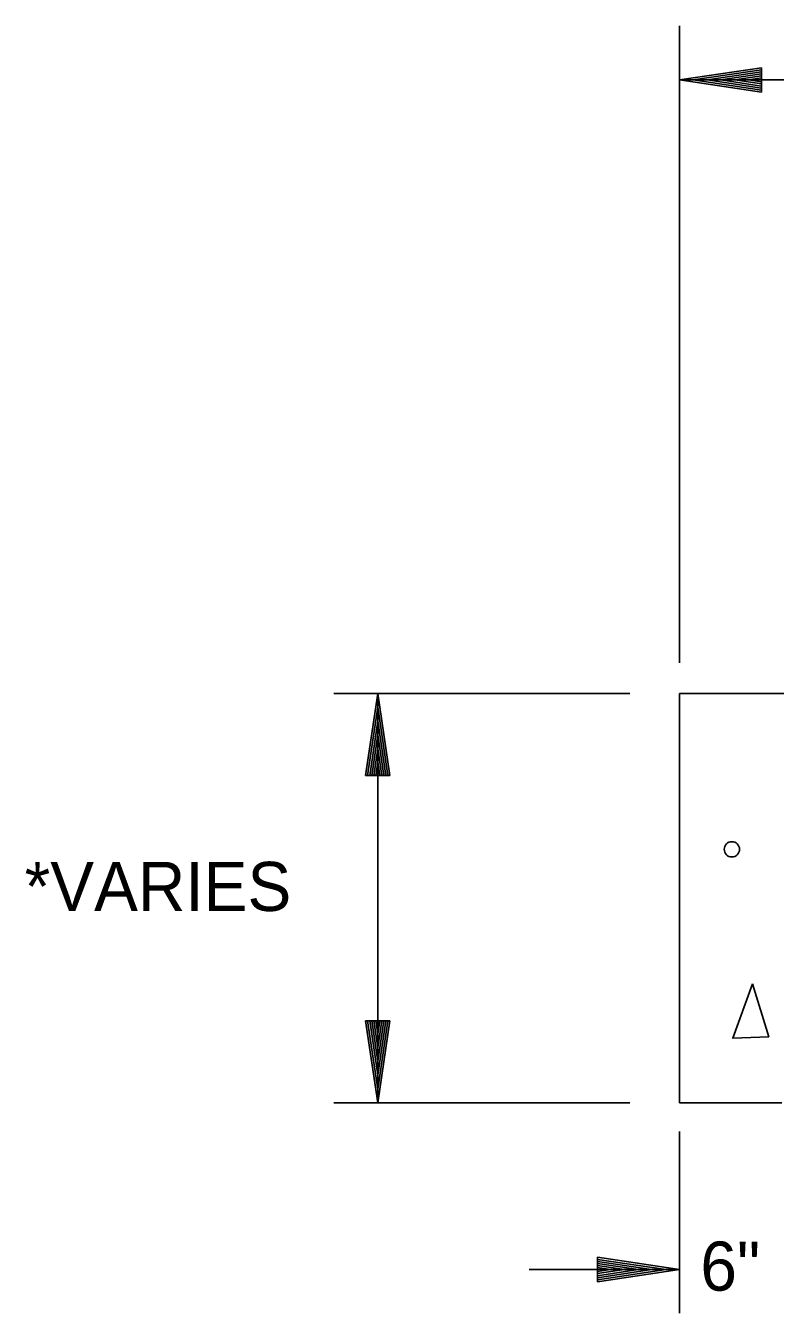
# Model space of a CAD drawing. Extents: x 3287 to 1767681, y -265 to 581440.
# Drawn here: x 3333.44 to 3351.75, y -240.26 to -208.81 of the extents above; entities that cross this region are included whole.
import ezdxf

# ---------------------------------------------------------------- set-up
doc = ezdxf.new("R2010")
doc.units = 0
doc.layers.add('Default', color=7, linetype='Continuous')

msp = doc.modelspace()

# ---------------------------------------------------------------- linework, layer by layer
at = {"layer": 'Default'}
for p, q in [((3349.405, -224.366), (3349.405, -208.806)), ((3351.407, -209.83), (3349.408, -210.13)), ((3351.407, -209.88), (3349.743, -210.13)), ((3351.407, -209.93), (3350.083, -210.13)), ((3351.407, -209.98), (3350.418, -210.13)), ((3351.407, -210.03), (3350.758, -210.13)), ((3351.407, -210.08), (3351.093, -210.13)), ((3351.407, -210.43), (3351.407, -209.83)), ((3349.405, -210.128), (3449.399, -210.128)), ((3351.407, -210.43), (3349.408, -210.13)), ((3351.407, -210.38), (3349.743, -210.13)), ((3351.407, -210.33), (3350.083, -210.13)), ((3351.407, -210.28), (3350.418, -210.13)), ((3351.407, -210.225), (3350.758, -210.13)), ((3351.407, -210.175), (3351.093, -210.13)), ((3348.198, -225.116), (3340.971, -225.116)), ((3341.738, -227.119), (3342.038, -225.119)), ((3342.338, -227.119), (3342.038, -225.119)), ((3342.039, -225.116), (3342.039, -235.116)), ((3349.405, -225.116), (3531.893, -225.116)), ((3349.405, -235.116), (3349.405, -225.116)), ((3341.788, -227.119), (3342.038, -225.449)), ((3342.288, -227.119), (3342.038, -225.449)), ((3341.843, -227.119), (3342.038, -225.794)), ((3342.238, -227.119), (3342.038, -225.794)), ((3341.893, -227.119), (3342.038, -226.129)), ((3342.188, -227.119), (3342.038, -226.129)), ((3341.943, -227.119), (3342.038, -226.469)), ((3342.138, -227.119), (3342.038, -226.469)), ((3341.993, -227.119), (3342.038, -226.799)), ((3342.088, -227.119), (3342.038, -226.799)), ((3341.738, -227.119), (3342.338, -227.119)), ((3341.738, -233.118), (3342.038, -235.118)), ((3342.338, -233.118), (3341.738, -233.118)), ((3341.788, -233.118), (3342.038, -234.783)), ((3341.843, -233.118), (3342.038, -234.438)), ((3341.893, -233.118), (3342.038, -234.103)), ((3341.943, -233.118), (3342.038, -233.768)), ((3341.993, -233.118), (3342.038, -233.433)), ((3342.338, -233.118), (3342.038, -235.118)), ((3342.138, -233.118), (3342.038, -233.768)), ((3342.238, -233.118), (3342.038, -234.438)), ((3342.288, -233.118), (3342.038, -234.783)), ((3342.188, -233.118), (3342.038, -234.103)), ((3342.088, -233.118), (3342.038, -233.433)), ((3348.198, -235.116), (3340.971, -235.116)), ((3351.905, -235.116), (3349.405, -235.116)), ((3349.405, -235.822), (3349.405, -240.26)), ((3347.408, -238.893), (3349.408, -239.193)), ((3347.408, -238.893), (3347.408, -239.493)), ((3347.408, -238.943), (3349.073, -239.193)), ((3347.408, -238.993), (3348.728, -239.193)), ((3347.408, -239.043), (3348.398, -239.193)), ((3349.405, -239.191), (3345.734, -239.191)), ((3347.408, -239.093), (3348.058, -239.193)), ((3347.408, -239.143), (3347.723, -239.193)), ((3347.408, -239.493), (3349.408, -239.193)), ((3347.408, -239.288), (3348.058, -239.193)), ((3347.408, -239.393), (3348.728, -239.193)), ((3347.408, -239.443), (3349.073, -239.193)), ((3347.408, -239.343), (3348.398, -239.193)), ((3347.408, -239.238), (3347.723, -239.193))]:
    msp.add_line(p, q, dxfattribs=at)
msp.add_lwpolyline([(3351.193, -232.213), (3350.708, -233.543), (3351.587, -233.503), (3351.193, -232.213)], dxfattribs=at)
msp.add_circle((3350.687, -228.926), 0.187, dxfattribs=at)

# ---------------------------------------------------------------- texts
for s, p in [('*VARIES', (3333.418, -230.432)), ('6"', (3349.918, -239.708))]:
    msp.add_text(s, height=1.2, dxfattribs=at).set_placement(p)

doc.saveas('drawing.dxf')
